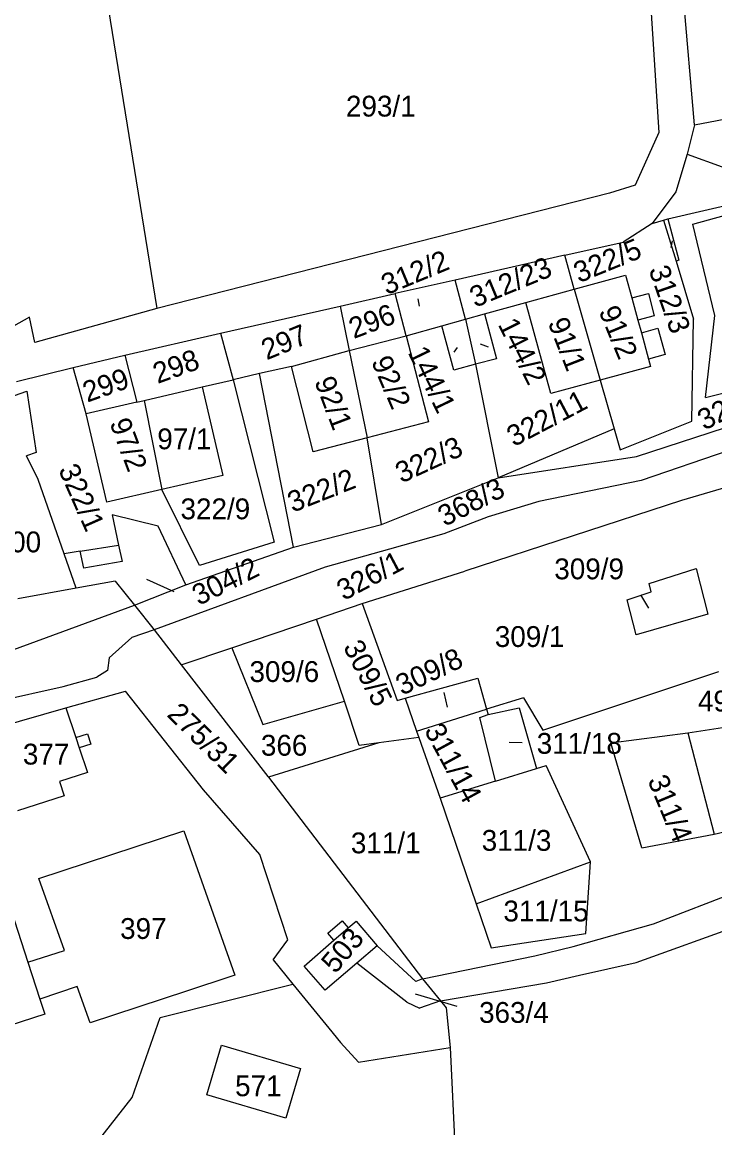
# Model space of a CAD drawing. Extents: x -805826 to -803822, y -1165880 to -1164382.
# Drawn here: x -805636 to -805522.9, y -1165156 to -1164975.4 of the extents above; entities that cross this region are included whole.
import ezdxf

# ---------------------------------------------------------------- set-up
doc = ezdxf.new("R2010")
doc.units = 0
for name, color, linetype in [('kn_celek - Cisla parcel pomocna', 7, 'Continuous'), ('kn_celek - Cisla pozemkovych parcel', 7, 'Continuous'), ('kn_celek - Cisla stavebnich parcel', 7, 'Continuous'), ('kn_celek - Hranice parcel', 7, 'Continuous'), ('kn_celek - Vnitrni kresby', 7, 'Continuous')]:
    doc.layers.add(name, color=color, linetype=linetype)

msp = doc.modelspace()

# ---------------------------------------------------------------- linework, layer by layer
at = {"layer": 'kn_celek - Cisla parcel pomocna'}
for p, q in [((-805529.89, -1165011.16), (-805530.08, -1165012.22)), ((-805571.11, -1165021.8), (-805571.34, -1165020.62)), ((-805564.98, -1165028.56), (-805565.51, -1165029.35)), ((-805561.23, -1165027.96), (-805559.91, -1165028.44)), ((-805615.7, -1165066.38), (-805611.22, -1165068.41)), ((-805533.65, -1165071.13), (-805535, -1165068.95)), ((-805566.55, -1165087.27), (-805567.11, -1165084.9)), ((-805556.49, -1165093.03), (-805554.38, -1165093.06)), ((-805571.84, -1165134.11), (-805565.01, -1165136.11))]:
    msp.add_line(p, q, dxfattribs=at)
at = {"layer": 'kn_celek - Hranice parcel'}
for p, q in [((-805534.95, -1164949.29), (-805532.02, -1164993.45)), ((-805624.11, -1164959.56), (-805613.98, -1165022.18)), ((-805526.2, -1164992.2), (-805529.03, -1164959.6)), ((-805526.2, -1164992.2), (-805506.38, -1164988.37)), ((-805532.02, -1164993.45), (-805535.93, -1165002.06)), ((-805526.2, -1164992.2), (-805527.44, -1164997.02)), ((-805527.44, -1164997.02), (-805529.26, -1165003.14)), ((-805527.44, -1164997.02), (-805521.7, -1164999.07)), ((-805535.93, -1165002.06), (-805540.12, -1165003.37)), ((-805540.12, -1165003.37), (-805613.98, -1165022.18)), ((-805529.26, -1165003.14), (-805533.14, -1165008.31)), ((-805530.57, -1165007.58), (-805511.35, -1165003.1)), ((-805526.47, -1165008.41), (-805511.07, -1165004.21)), ((-805533.14, -1165008.31), (-805531.29, -1165007.79)), ((-805531.29, -1165007.79), (-805530.57, -1165007.58)), ((-805531.29, -1165007.79), (-805529.23, -1165014.46)), ((-805530.57, -1165007.58), (-805528.8, -1165014.32)), ((-805533.14, -1165008.31), (-805537.88, -1165011.37)), ((-805522.91, -1165023.34), (-805526.47, -1165008.41)), ((-805547.37, -1165013.51), (-805537.88, -1165011.37)), ((-805547.37, -1165013.51), (-805565.29, -1165017.55)), ((-805545.88, -1165019.04), (-805547.37, -1165013.51)), ((-805528.8, -1165014.32), (-805529.23, -1165014.46)), ((-805529.23, -1165014.46), (-805526.38, -1165023.94)), ((-805545.88, -1165019.04), (-805537.46, -1165016.76)), ((-805537.46, -1165016.76), (-805536.47, -1165020.43)), ((-805565.29, -1165017.55), (-805575.07, -1165019.76)), ((-805563.6, -1165023.94), (-805565.29, -1165017.55)), ((-805584.09, -1165021.8), (-805575.07, -1165019.76)), ((-805573.3, -1165026.65), (-805575.07, -1165019.76)), ((-805553.75, -1165021.23), (-805545.88, -1165019.04)), ((-805545.88, -1165019.04), (-805541.62, -1165033.88)), ((-805536.47, -1165020.43), (-805533.75, -1165019.73)), ((-805533.75, -1165019.73), (-805532.8, -1165023.41)), ((-805613.98, -1165022.18), (-805633.92, -1165027.74)), ((-805603.59, -1165026.21), (-805584.09, -1165021.8)), ((-805584.09, -1165021.8), (-805582.58, -1165029.08)), ((-805560.5, -1165023.06), (-805553.75, -1165021.23)), ((-805549.69, -1165036.08), (-805553.75, -1165021.23)), ((-805634.8, -1165023.61), (-805659.45, -1165037.34)), ((-805633.92, -1165027.74), (-805634.8, -1165023.61)), ((-805567.47, -1165025.01), (-805563.6, -1165023.94)), ((-805563.6, -1165023.94), (-805560.5, -1165023.06)), ((-805563.6, -1165023.94), (-805561.95, -1165031.28)), ((-805560.5, -1165023.06), (-805558.55, -1165030.4)), ((-805532.8, -1165023.41), (-805535.47, -1165024.1)), ((-805535.47, -1165024.1), (-805534.9, -1165026.19)), ((-805526.63, -1165040.59), (-805526.38, -1165023.94)), ((-805524.44, -1165036.73), (-805522.91, -1165023.34)), ((-805573.3, -1165026.65), (-805567.47, -1165025.01)), ((-805565.52, -1165032.27), (-805567.47, -1165025.01)), ((-805534.9, -1165026.19), (-805532.21, -1165025.43)), ((-805532.21, -1165025.43), (-805531, -1165029.71)), ((-805619.22, -1165029.82), (-805603.59, -1165026.21)), ((-805603.59, -1165026.21), (-805601.55, -1165033.85)), ((-805582.58, -1165029.08), (-805573.3, -1165026.65)), ((-805573.3, -1165026.65), (-805569.65, -1165040.69)), ((-805592.01, -1165031.66), (-805582.58, -1165029.08)), ((-805582.58, -1165029.08), (-805579.65, -1165043.29)), ((-805627.65, -1165031.81), (-805619.22, -1165029.82)), ((-805619.22, -1165029.82), (-805617.28, -1165037.5)), ((-805561.95, -1165031.28), (-805565.52, -1165032.27)), ((-805558.55, -1165030.4), (-805561.95, -1165031.28)), ((-805561.95, -1165031.28), (-805558.27, -1165049.87)), ((-805531, -1165029.71), (-805533.74, -1165030.47)), ((-805533.74, -1165030.47), (-805533.42, -1165031.67)), ((-805636.9, -1165034.1), (-805627.65, -1165031.81)), ((-805625.55, -1165039.4), (-805627.65, -1165031.81)), ((-805597.26, -1165032.83), (-805601.55, -1165033.85)), ((-805592.01, -1165031.66), (-805597.26, -1165032.83)), ((-805591.7, -1165061.19), (-805597.26, -1165032.83)), ((-805588.47, -1165045.59), (-805592.01, -1165031.66)), ((-805533.42, -1165031.67), (-805541.62, -1165033.88)), ((-805524.44, -1165036.73), (-805504.2, -1165031.53)), ((-805606.6, -1165035.01), (-805601.55, -1165033.85)), ((-805601.55, -1165033.85), (-805594.86, -1165060.34)), ((-805541.62, -1165033.88), (-805549.69, -1165036.08)), ((-805541.62, -1165033.88), (-805539.32, -1165041.83)), ((-805655.88, -1165042.77), (-805635.21, -1165035.71)), ((-805635.21, -1165035.71), (-805633.67, -1165045.73)), ((-805616.07, -1165037.2), (-805606.6, -1165035.01)), ((-805606.6, -1165035.01), (-805603.25, -1165049.48)), ((-805535.71, -1165046.34), (-805503.53, -1165035.89)), ((-805617.28, -1165037.5), (-805625.55, -1165039.4)), ((-805617.28, -1165037.5), (-805616.07, -1165037.2)), ((-805616.07, -1165037.2), (-805613.2, -1165051.77)), ((-805622.17, -1165053.83), (-805625.55, -1165039.4)), ((-805569.65, -1165040.69), (-805579.65, -1165043.29)), ((-805539.32, -1165041.83), (-805558.27, -1165049.87)), ((-805539.32, -1165041.83), (-805538.38, -1165045.27)), ((-805538.38, -1165045.27), (-805526.63, -1165040.59)), ((-805579.65, -1165043.29), (-805588.47, -1165045.59)), ((-805577.33, -1165057.46), (-805579.65, -1165043.29)), ((-805633.67, -1165045.73), (-805635.3, -1165046.28)), ((-805520.63, -1165045.37), (-805534.93, -1165050.28)), ((-805633.35, -1165050.12), (-805635.3, -1165046.28)), ((-805558.27, -1165049.87), (-805535.71, -1165046.34)), ((-805629.14, -1165062.24), (-805633.35, -1165050.12)), ((-805603.25, -1165049.48), (-805613.2, -1165051.77)), ((-805577.33, -1165057.46), (-805558.27, -1165049.87)), ((-805534.93, -1165050.28), (-805551.65, -1165053.71)), ((-805519.07, -1165050.81), (-805528.36, -1165053.56)), ((-805613.2, -1165051.77), (-805622.17, -1165053.83)), ((-805607.02, -1165064.18), (-805613.2, -1165051.77)), ((-805528.36, -1165053.56), (-805563.72, -1165065.1)), ((-805551.65, -1165053.71), (-805559.92, -1165056.22)), ((-805613.78, -1165057.72), (-805621.31, -1165055.87)), ((-805621.31, -1165055.87), (-805620.23, -1165060.82)), ((-805559.92, -1165056.22), (-805567.12, -1165058.97)), ((-805609.27, -1165067.32), (-805613.78, -1165057.72)), ((-805591.7, -1165061.19), (-805577.33, -1165057.46)), ((-805567.12, -1165058.97), (-805576, -1165061.47)), ((-805626.54, -1165061.8), (-805629.14, -1165062.24)), ((-805625.94, -1165064.6), (-805626.54, -1165061.8)), ((-805620.23, -1165060.82), (-805619.65, -1165063.52)), ((-805609.27, -1165067.32), (-805591.7, -1165061.19)), ((-805594.86, -1165060.34), (-805607.02, -1165064.18)), ((-805576, -1165061.47), (-805586.54, -1165064.43)), ((-805627.18, -1165067.88), (-805629.14, -1165062.24)), ((-805619.65, -1165063.52), (-805625.94, -1165064.6)), ((-805586.54, -1165064.43), (-805614.43, -1165074.64)), ((-805580.47, -1165070.39), (-805563.72, -1165065.1)), ((-805533.64, -1165067.11), (-805525.95, -1165064.67)), ((-805525.95, -1165064.67), (-805524.02, -1165072.1)), ((-805620.79, -1165066.73), (-805627.18, -1165067.88)), ((-805620.79, -1165066.73), (-805617.65, -1165070.65)), ((-805617.65, -1165070.65), (-805609.27, -1165067.32)), ((-805533.29, -1165068.46), (-805533.64, -1165067.11)), ((-805627.18, -1165067.88), (-805636.7, -1165069.59)), ((-805537.2, -1165069.78), (-805533.29, -1165068.46)), ((-805668.7, -1165089.31), (-805617.65, -1165070.65)), ((-805617.65, -1165070.65), (-805614.43, -1165074.64)), ((-805587.95, -1165072.92), (-805580.47, -1165070.39)), ((-805580.47, -1165070.39), (-805574.74, -1165086.18)), ((-805535.75, -1165075.48), (-805537.2, -1165069.78)), ((-805524.02, -1165072.1), (-805535.75, -1165075.48)), ((-805614.43, -1165074.64), (-805618.08, -1165075.93)), ((-805614.43, -1165074.64), (-805610, -1165080.37)), ((-805601.73, -1165077.58), (-805587.95, -1165072.92)), ((-805583.37, -1165086.29), (-805587.95, -1165072.92)), ((-805618.08, -1165075.93), (-805621.78, -1165079.21)), ((-805610, -1165080.37), (-805601.73, -1165077.58)), ((-805601.73, -1165077.58), (-805596.7, -1165090.13)), ((-805621.78, -1165079.21), (-805622.04, -1165081.28)), ((-805622.04, -1165081.28), (-805623.78, -1165082.41)), ((-805610, -1165080.37), (-805595.86, -1165098.62)), ((-805550.96, -1165091.05), (-805522.25, -1165081.49)), ((-805629.3, -1165083.94), (-805623.78, -1165082.41)), ((-805573.44, -1165085.82), (-805561.62, -1165082.56)), ((-805561.62, -1165082.56), (-805560.17, -1165087.62)), ((-805655.57, -1165089.73), (-805629.3, -1165083.94)), ((-805628.85, -1165087.41), (-805619.1, -1165084.66)), ((-805606.4, -1165100.77), (-805619.1, -1165084.66)), ((-805596.7, -1165090.13), (-805583.37, -1165086.29)), ((-805580.96, -1165093.55), (-805583.37, -1165086.29)), ((-805574.74, -1165086.18), (-805573.44, -1165085.82)), ((-805573.44, -1165085.82), (-805571.58, -1165091.19)), ((-805554.15, -1165085.75), (-805560.17, -1165087.62)), ((-805554.15, -1165085.75), (-805550.96, -1165091.05)), ((-805641.01, -1165090.89), (-805628.85, -1165087.41)), ((-805628.85, -1165087.41), (-805627.22, -1165092.23)), ((-805571.58, -1165091.19), (-805560.17, -1165087.62)), ((-805561.25, -1165088.95), (-805559.92, -1165088.5)), ((-805558.71, -1165099.37), (-805561.25, -1165088.95)), ((-805560.17, -1165087.62), (-805559.92, -1165088.5)), ((-805559.92, -1165088.5), (-805554.83, -1165087.38)), ((-805554.83, -1165087.38), (-805552.03, -1165097.32)), ((-805527.3, -1165091.46), (-805518.7, -1165090.14)), ((-805627.22, -1165092.23), (-805625.33, -1165091.63)), ((-805625.33, -1165091.63), (-805624.78, -1165093.35)), ((-805571.23, -1165092.22), (-805577.73, -1165093.11)), ((-805571.58, -1165091.19), (-805571.23, -1165092.22)), ((-805571.23, -1165092.22), (-805567.73, -1165102.14)), ((-805539.89, -1165093.12), (-805527.3, -1165091.46)), ((-805527.3, -1165091.46), (-805523.03, -1165108.02)), ((-805624.78, -1165093.35), (-805626.65, -1165093.94)), ((-805626.65, -1165093.94), (-805625.29, -1165097.96)), ((-805577.73, -1165093.11), (-805595.77, -1165098.74)), ((-805577.73, -1165093.11), (-805580.96, -1165093.55)), ((-805534.84, -1165110.23), (-805539.89, -1165093.12)), ((-805625.29, -1165097.96), (-805629.89, -1165099.44)), ((-805558.71, -1165099.37), (-805552.03, -1165097.32)), ((-805552.03, -1165097.32), (-805550.43, -1165096.82)), ((-805543.18, -1165112.55), (-805550.43, -1165096.82)), ((-805629.89, -1165099.44), (-805629.15, -1165101.74)), ((-805595.86, -1165098.62), (-805595.77, -1165098.74)), ((-805595.77, -1165098.74), (-805570.62, -1165131.67)), ((-805558.71, -1165099.37), (-805567.73, -1165102.14)), ((-805629.15, -1165101.74), (-805636.77, -1165104.19)), ((-805597.18, -1165111.34), (-805606.4, -1165100.77)), ((-805567.73, -1165102.14), (-805561.87, -1165119.41)), ((-805532.9, -1165122.69), (-805488.62, -1165105.47)), ((-805523.03, -1165108.02), (-805514.95, -1165106.11)), ((-805633.27, -1165115.26), (-805609.61, -1165107.47)), ((-805609.61, -1165107.47), (-805601.24, -1165131.06)), ((-805534.84, -1165110.23), (-805523.03, -1165108.02)), ((-805592.63, -1165125.26), (-805597.18, -1165111.34)), ((-805561.87, -1165119.41), (-805543.18, -1165112.55)), ((-805543.95, -1165124.25), (-805543.18, -1165112.55)), ((-805629.09, -1165127.01), (-805633.27, -1165115.26)), ((-805638.87, -1165117.13), (-805635.04, -1165128.95)), ((-805561.87, -1165119.41), (-805559.43, -1165126.6)), ((-805535.76, -1165128.97), (-805514.21, -1165121.19)), ((-805586.1, -1165124.19), (-805583.76, -1165122.16)), ((-805583.76, -1165122.16), (-805582.74, -1165123.32)), ((-805582.74, -1165123.32), (-805581.48, -1165122.24)), ((-805581.48, -1165122.24), (-805578.04, -1165126.23)), ((-805546.02, -1165126.34), (-805532.9, -1165122.69)), ((-805585.09, -1165125.35), (-805586.1, -1165124.19)), ((-805559.43, -1165126.6), (-805543.95, -1165124.25)), ((-805635.04, -1165128.95), (-805629.09, -1165127.01)), ((-805595.03, -1165128.52), (-805592.63, -1165125.26)), ((-805589.95, -1165129.57), (-805585.09, -1165125.35)), ((-805578.04, -1165126.23), (-805581.36, -1165129.08)), ((-805571.74, -1165132.06), (-805578.04, -1165126.23)), ((-805552.27, -1165127.87), (-805546.02, -1165126.34)), ((-805595.03, -1165128.52), (-805591.8, -1165132.5)), ((-805570.62, -1165131.67), (-805552.27, -1165127.87)), ((-805635.04, -1165128.95), (-805633.09, -1165134.96)), ((-805586.52, -1165133.5), (-805589.95, -1165129.57)), ((-805581.36, -1165129.08), (-805586.52, -1165133.5)), ((-805573.17, -1165135.45), (-805581.36, -1165129.08)), ((-805544.99, -1165131.05), (-805535.76, -1165128.97)), ((-805601.73, -1165131.22), (-805609.18, -1165133.67)), ((-805601.24, -1165131.06), (-805601.73, -1165131.22)), ((-805570.62, -1165131.67), (-805571.74, -1165132.06)), ((-805570.62, -1165131.67), (-805567.7, -1165135.25)), ((-805567.7, -1165135.25), (-805550.41, -1165132.31)), ((-805550.41, -1165132.31), (-805544.99, -1165131.05)), ((-805626.99, -1165132.91), (-805633.09, -1165134.96)), ((-805624.86, -1165138.83), (-805626.99, -1165132.91)), ((-805609.18, -1165133.67), (-805624.86, -1165138.83)), ((-805613.44, -1165137.96), (-805591.8, -1165132.5)), ((-805591.8, -1165132.5), (-805585.94, -1165139.7)), ((-805633.09, -1165134.96), (-805632.28, -1165137.44)), ((-805573.17, -1165135.45), (-805571.14, -1165136.45)), ((-805567.7, -1165135.25), (-805571.14, -1165136.45)), ((-805567.7, -1165135.25), (-805566.77, -1165136.4)), ((-805632.28, -1165137.44), (-805640.97, -1165140.23)), ((-805566.77, -1165136.4), (-805566.11, -1165142.85)), ((-805618.03, -1165151.04), (-805613.44, -1165137.96)), ((-805585.94, -1165139.7), (-805584.01, -1165142.05)), ((-805605.83, -1165150.61), (-805603.44, -1165142.5)), ((-805603.44, -1165142.5), (-805590.56, -1165146.29)), ((-805584.01, -1165142.05), (-805581.05, -1165145.24)), ((-805581.05, -1165145.24), (-805566.11, -1165142.85)), ((-805566.11, -1165142.85), (-805564.24, -1165183.13)), ((-805590.56, -1165146.29), (-805592.95, -1165154.41)), ((-805626.04, -1165161.21), (-805618.03, -1165151.04)), ((-805592.95, -1165154.41), (-805605.83, -1165150.61))]:
    msp.add_line(p, q, dxfattribs=at)
at = {"layer": 'kn_celek - Vnitrni kresby'}
for p, q in [((-805536.47, -1165020.43), (-805535.47, -1165024.1)), ((-805534.9, -1165026.19), (-805533.74, -1165030.47)), ((-805626.54, -1165061.8), (-805620.23, -1165060.82)), ((-805627.22, -1165092.23), (-805626.65, -1165093.94)), ((-805585.09, -1165125.35), (-805582.74, -1165123.32))]:
    msp.add_line(p, q, dxfattribs=at)

# ---------------------------------------------------------------- texts
at = {"layer": 'kn_celek - Cisla parcel pomocna'}
for s, rotation, p in [('312/2', 22.518, (-805576.47, -1165020.04)), ('312/3', 289.233, (-805533.74, -1165015.84)), ('144/2', 296.622, (-805558.38, -1165024.8)), ('144/1', 295.758, (-805573.08, -1165029.35)), ('304/2', 26.64, (-805607.14, -1165070.77)), ('309/8', 25.497, (-805573.96, -1165085.44))]:
    msp.add_text(s, height=3.4, rotation=rotation, dxfattribs=at).set_placement(p)
for s, p in [('309/9', (-805549.11, -1165066.41)), ('491', (-805525.66, -1165087.98)), ('311/18', (-805551.98, -1165094.9)), ('363/4', (-805561.39, -1165138.83))]:
    msp.add_text(s, height=3.4, dxfattribs=at).set_placement(p)
at = {"layer": 'kn_celek - Cisla pozemkovych parcel'}
for s, height, p in [('293/1', 3.4, (-805583.12, -1164990.86)), ('312/3', 0.005, (-805529.89, -1165011.16)), ('312/2', 0.005, (-805571.11, -1165021.8)), ('322/9', 3.4, (-805610.13, -1165056.61)), ('300', 3.4, (-805640.47, -1165062.01)), ('304/2', 0.005, (-805615.7, -1165066.38)), ('309/9', 0.005, (-805533.65, -1165071.13)), ('309/1', 3.4, (-805558.82, -1165077.46)), ('309/6', 3.4, (-805598.87, -1165083.18)), ('309/8', 0.005, (-805566.55, -1165087.27)), ('366', 3.4, (-805597.01, -1165095.21)), ('311/18', 0.005, (-805556.49, -1165093.03)), ('311/3', 3.4, (-805560.96, -1165110.74)), ('311/1', 3.4, (-805582.32, -1165111.15)), ('311/15', 3.4, (-805557.42, -1165122.27)), ('363/4', 0.005, (-805571.84, -1165134.11))]:
    msp.add_text(s, height=height, dxfattribs=at).set_placement(p)
for s, rotation, p in [('322/5', 22.23, (-805545.08, -1165018.08)), ('312/23', 22.518, (-805562.03, -1165022.1)), ('296', 20.745, (-805581.85, -1165027.19)), ('297', 22.23, (-805596.07, -1165030.67)), ('298', 20.052, (-805613.87, -1165034.53)), ('299', 19.656, (-805625.36, -1165037.58)), ('322/4', 26.703, (-805524.63, -1165042.16)), ('322/11', 27.846, (-805555.71, -1165044.85)), ('322/3', 24.696, (-805574.06, -1165050.79)), ('322/1', 293.931, (-805630.13, -1165048.5)), ('322/2', 21.654, (-805591.81, -1165055.56)), ('368/3', 27.045, (-805567, -1165057.86)), ('326/1', 27.963, (-805583.47, -1165069.97)), ('309/5', 297.423, (-805583.65, -1165077.43)), ('275/31', 315.585, (-805612.51, -1165088.65)), ('311/14', 298.566, (-805570.42, -1165091.08)), ('311/4', 292.608, (-805533.93, -1165099.21))]:
    msp.add_text(s, height=3.4, rotation=rotation, dxfattribs=at).set_placement(p)
at = {"layer": 'kn_celek - Cisla stavebnich parcel'}
for s, rotation, p in [('91/2', 292.491, (-805541.91, -1165022.61)), ('91/1', 291.294, (-805550.21, -1165024.47)), ('92/2', 293.409, (-805579.05, -1165030.83)), ('92/1', 290.835, (-805588.32, -1165034.07)), ('97/2', 290.601, (-805621.75, -1165040.85)), ('503', 49.905, (-805584.85, -1165130.95))]:
    msp.add_text(s, height=3.4, rotation=rotation, dxfattribs=at).set_placement(p)
for s, height, p in [('144/1', 0.005, (-805564.98, -1165028.56)), ('144/2', 0.005, (-805561.23, -1165027.96)), ('97/1', 3.4, (-805613.92, -1165045.18)), ('377', 3.4, (-805635.86, -1165096.66)), ('397', 3.4, (-805619.99, -1165125.13)), ('571', 3.4, (-805601.22, -1165150.81))]:
    msp.add_text(s, height=height, dxfattribs=at).set_placement(p)

doc.saveas('drawing.dxf')
